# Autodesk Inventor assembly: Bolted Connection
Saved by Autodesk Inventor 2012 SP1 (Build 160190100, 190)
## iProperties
Created: 2006-09
Part Number: Bolted Connection
Document SubType Name: Assembly
ClientObjectVersion: 1
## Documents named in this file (3)
- D:\Backup\CMU Work Temp\XX\Inv2012DynSim\Sub-Assemblies\Bolted Connection1.iam
- D:\Backup\CMU Work Temp\XX\Inv2012DynSim\Parts\M5-16.ipt
- D:\Backup\CMU Work Temp\XX\Inv2012DynSim\Parts\M5.ipt
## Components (2 placed, 2 different names)
1. Indented Hex Head Machine Screw - Metric M5 x 0.8 x 16:1
2. DIN 6923 M5:1
